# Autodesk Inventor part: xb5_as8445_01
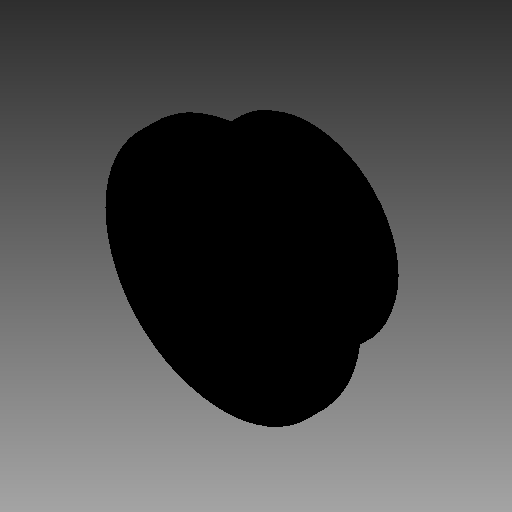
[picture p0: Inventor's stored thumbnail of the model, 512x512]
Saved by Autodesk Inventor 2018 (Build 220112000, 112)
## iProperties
Company: TraceParts S.A.
Created: 2018-04
Part Number: xb5_as8445_01
Checked By: TraceParts S.A.
Material: Generic
Catalog Web Link: www.traceparts.com
Document SubType Name: Modeling
Designer: TraceParts
Density: 1 g/cm^3
Appearance: Default
Author: TraceParts
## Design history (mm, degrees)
feature "xb5_as8445_01.ipt"
body "Solid1"
